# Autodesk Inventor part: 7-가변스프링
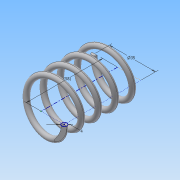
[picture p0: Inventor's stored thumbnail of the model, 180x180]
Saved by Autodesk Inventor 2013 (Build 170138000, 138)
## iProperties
Created: 2015-03
Part Number: 7-가변스프링
Material: 강철, 탄소
Document SubType Name: Modeling
Designer: Administrator
Density: 7.87 g/cm^3
Mass: 48.2733 g
Surface Area: 62.0009 cm^2
Volume: 6.13384 cm^3
Author: Administrator
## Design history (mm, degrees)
sketch "스케치1"
  geometry: L1 (0, 0)-(17.5, 0); L2 (17.5, 0)-(17.5, 43.5); L3 (17.5, 43.5)-(0, 43.5); L4 (0, 43.5)-(0, 0); C1 r 2 at (17.5, 0); 1 further point
  constraints: 8 end point, 2 coincident, 2 parallel, 1 centre point, 1 horizontal, 1 perpendicular
  dimensions: "d0" = 43.5 distance of L3.end L1.start (derived); "d2" = 35 diameter of L2 L4; "d3" = 4 diameter of C1
feature "코일1" pitch "d4" = 10; turns "d6" = 4.5; dims "d5" = 43.5 (= d0), "d7" = 0, angle "d8" = 90 deg, angle "d9" = 90 deg, "d10" = 0, "d11" = 0
sketch "스케치2"
  geometry: L1 (-19.5, 0)-(-15.5, 0) reference; 1 further point
  constraints: 1 horizontal alignment
extrude "돌출1" cut sketch "스케치2" stored distance "d12" = 10; taper "d13" = 0 deg
node "작업 평면1"
sketch "스케치3"
  geometry: L1 (-19.5, 0)-(-15.5, 0) reference; 1 further point
  constraints: 1 horizontal alignment
extrude "돌출2" cut sketch "스케치3" stored distance "d15" = 10; taper "d16" = 0 deg
node "솔리드1"
node "절단 모서리 투영1"
node "절단 모서리 투영2"
other parameters: "d14" = -43.5 (= -d0)
